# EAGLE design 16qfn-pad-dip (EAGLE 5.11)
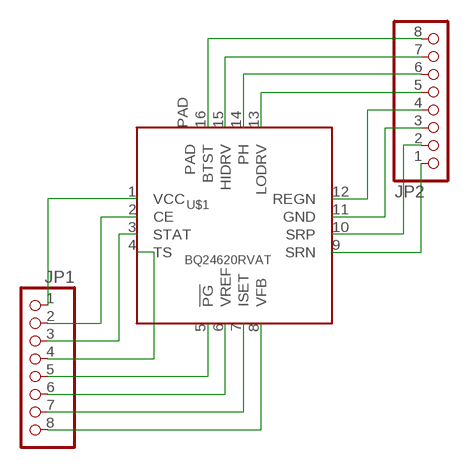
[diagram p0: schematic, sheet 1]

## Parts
JP1  PINHD-1X8  [1X08]
JP2  PINHD-1X8  [1X08]
U$1  BQ24620RVAT  [QFN16-3.5X3.5-0.5PITCH]

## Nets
N$1: JP1.1 U$1.1(VCC)
N$2: JP1.2 U$1.2(CE)
N$3: JP1.3 U$1.3(STAT)
N$4: JP1.4 U$1.4(TS)
N$5: JP1.5 U$1.5(!PG)
N$6: JP1.6 U$1.6(VREF)
N$7: JP1.7 U$1.7(ISET)
N$8: JP1.8 U$1.8(VFB)
N$9: JP2.1 U$1.9(SRN)
N$10: JP2.2 U$1.10(SRP)
N$11: JP2.3 U$1.11(GND)
N$12: JP2.4 U$1.12(REGN)
N$13: JP2.5 U$1.13(LODRV)
N$14: JP2.6 U$1.14(PH)
N$15: JP2.7 U$1.15(HIDRV)
N$16: JP2.8 U$1.16(BTST)
Unconnected: U$1.PAD

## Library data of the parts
JP1 JP2 = pinhead:PINHD-1X8: PIN HEADER
U$1 = trl:BQ24620RVAT

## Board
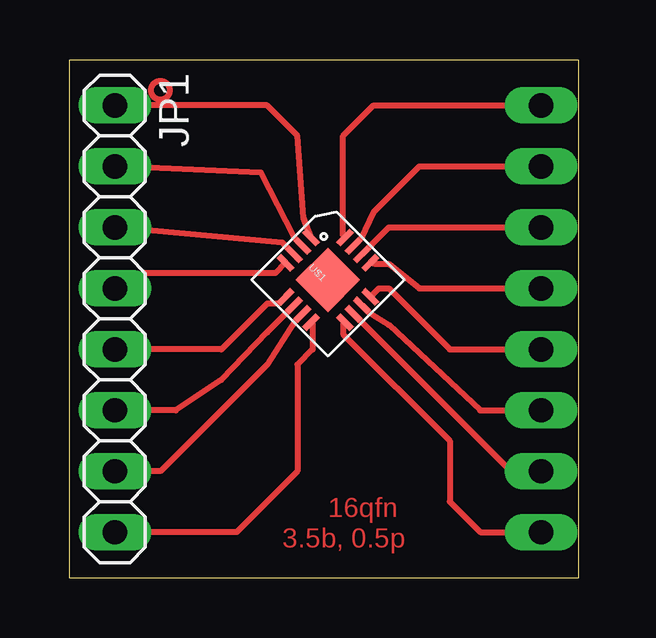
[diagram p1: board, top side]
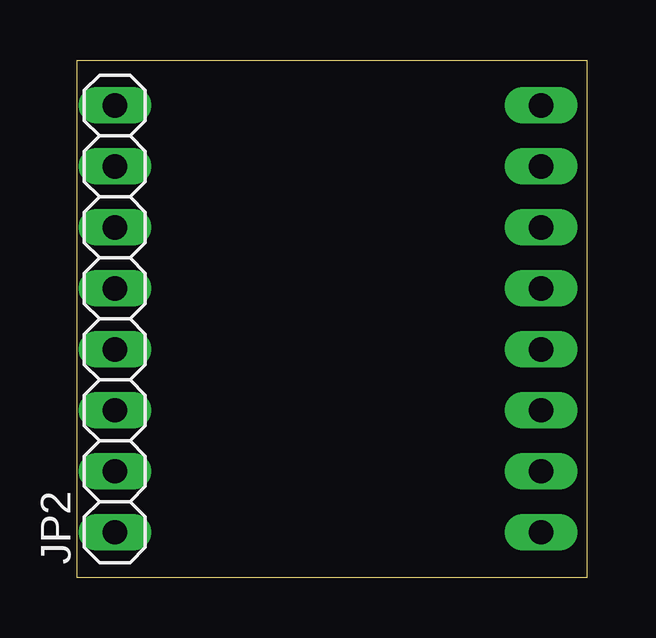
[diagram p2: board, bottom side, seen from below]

Size 21.26 x 21.58 mm. Coordinates in mm from the lower left corner, seen from the top.
Outline: 0,0 21.26,0 21.26,21.58 0,21.58 0,0
Copper layers (1*16): Top 0.035mm / dielectric 1.5mm / Bottom 0.035mm
Design rules "default": minimum track width 10mil, minimum drill 0.6mm, track to track 8mil, track to pad 8mil, pad to pad 8mil, via to via 8mil, smd to smd 8mil, copper to edge 40mil, drill to drill 8mil, minimum pad ring 10mil, minimum via ring 8mil, stop-mask expansion 4mil, vias tented up to drill 0mil, thermal gap 10mil

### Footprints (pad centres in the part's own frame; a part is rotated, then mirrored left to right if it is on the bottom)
1X08 = drill 1.016 long: 1 -8.89,0; 2 -6.35,0; 3 -3.81,0; 4 -1.27,0; 5 1.27,0; 6 3.81,0; 7 6.35,0; 8 8.89,0
QFN16-3.5X3.5-0.5PITCH = smd 0.8 x 0.25: 1 -2,1; 2 -2,0.5; 3 -2,0; 4 -2,-0.5; 9 1.5,-0.5; 10 1.5,0; 11 1.5,0.5; 12 1.5,1 | smd 0.25 x 0.8: 5 -1,-1.5; 6 -0.5,-1.5; 7 0,-1.5; 8 0.5,-1.5; 13 0.5,2; 14 0,2; 15 -0.5,2; 16 -1,2 | smd 1.9 x 1.9: PAD -0.25,0.25

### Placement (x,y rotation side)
JP1  1.91,10.79 270 top
JP2  19.68,10.79 90 bottom
U$1  10.79,12.06 315 top

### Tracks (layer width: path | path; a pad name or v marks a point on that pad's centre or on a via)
N$1
  Top 0.254: U$1.1 9.78,15 9.53,18.41 8.26,19.68 JP1.1
N$2
  Top 0.254: U$1.2 9.4,14.17 8,16.89 JP1.2
N$3
  Top 0.254: U$1.3 8.89,13.97 JP1.3
N$4
  Top 0.254: U$1.4 8.6,12.7 3.17,12.7 2.54,12.06 JP1.4
N$5
  Top 0.254: U$1.5 8.75,11.43 8.26,11.43 6.35,9.53 JP1.5
N$6
  Top 0.254: U$1.6 8.26,10.23 6.35,8.26 4.45,6.99 JP1.6
N$7
  Top 0.254: U$1.7 9.4,10.67 8.26,8.89 3.81,4.45 JP1.7
N$8
  Top 0.254: U$1.8 10.16,10.58 10.16,9.53 9.53,8.89 9.53,4.45 6.99,1.91 JP1.8
N$9
  Top 0.254: U$1.9 11.43,10.58 11.43,10.16 15.88,5.71 15.88,3.17 17.14,1.91 JP2.1
N$10
  Top 0.254: U$1.10 18.41,4.45 JP2.2
N$11
  Top 0.254: U$1.11 12.52,11.05 13.34,10.54 17.14,6.99 JP2.3
N$12
  Top 0.254: U$1.12 12.92,12.06 13.34,12.06 15.88,9.53 JP2.4
N$13
  Top 0.254: U$1.13 12.77,13.08 13.34,13.08 14.61,12.06 JP2.5
N$14
  Top 0.254: U$1.14 13.34,14.61 JP2.6
N$15
  Top 0.254: U$1.15 12.19,14.17 12.7,15.24 14.61,17.14 JP2.7
N$16
  Top 0.254: U$1.16 11.43,14.26 11.43,18.41 12.7,19.68 JP2.8
(copper drawn outside any net)
  shapes: Top circle x1

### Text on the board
Top: 16qfn | 3.5b, 0.5p
tDocu: testing solder pasting 0.5mm pitch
